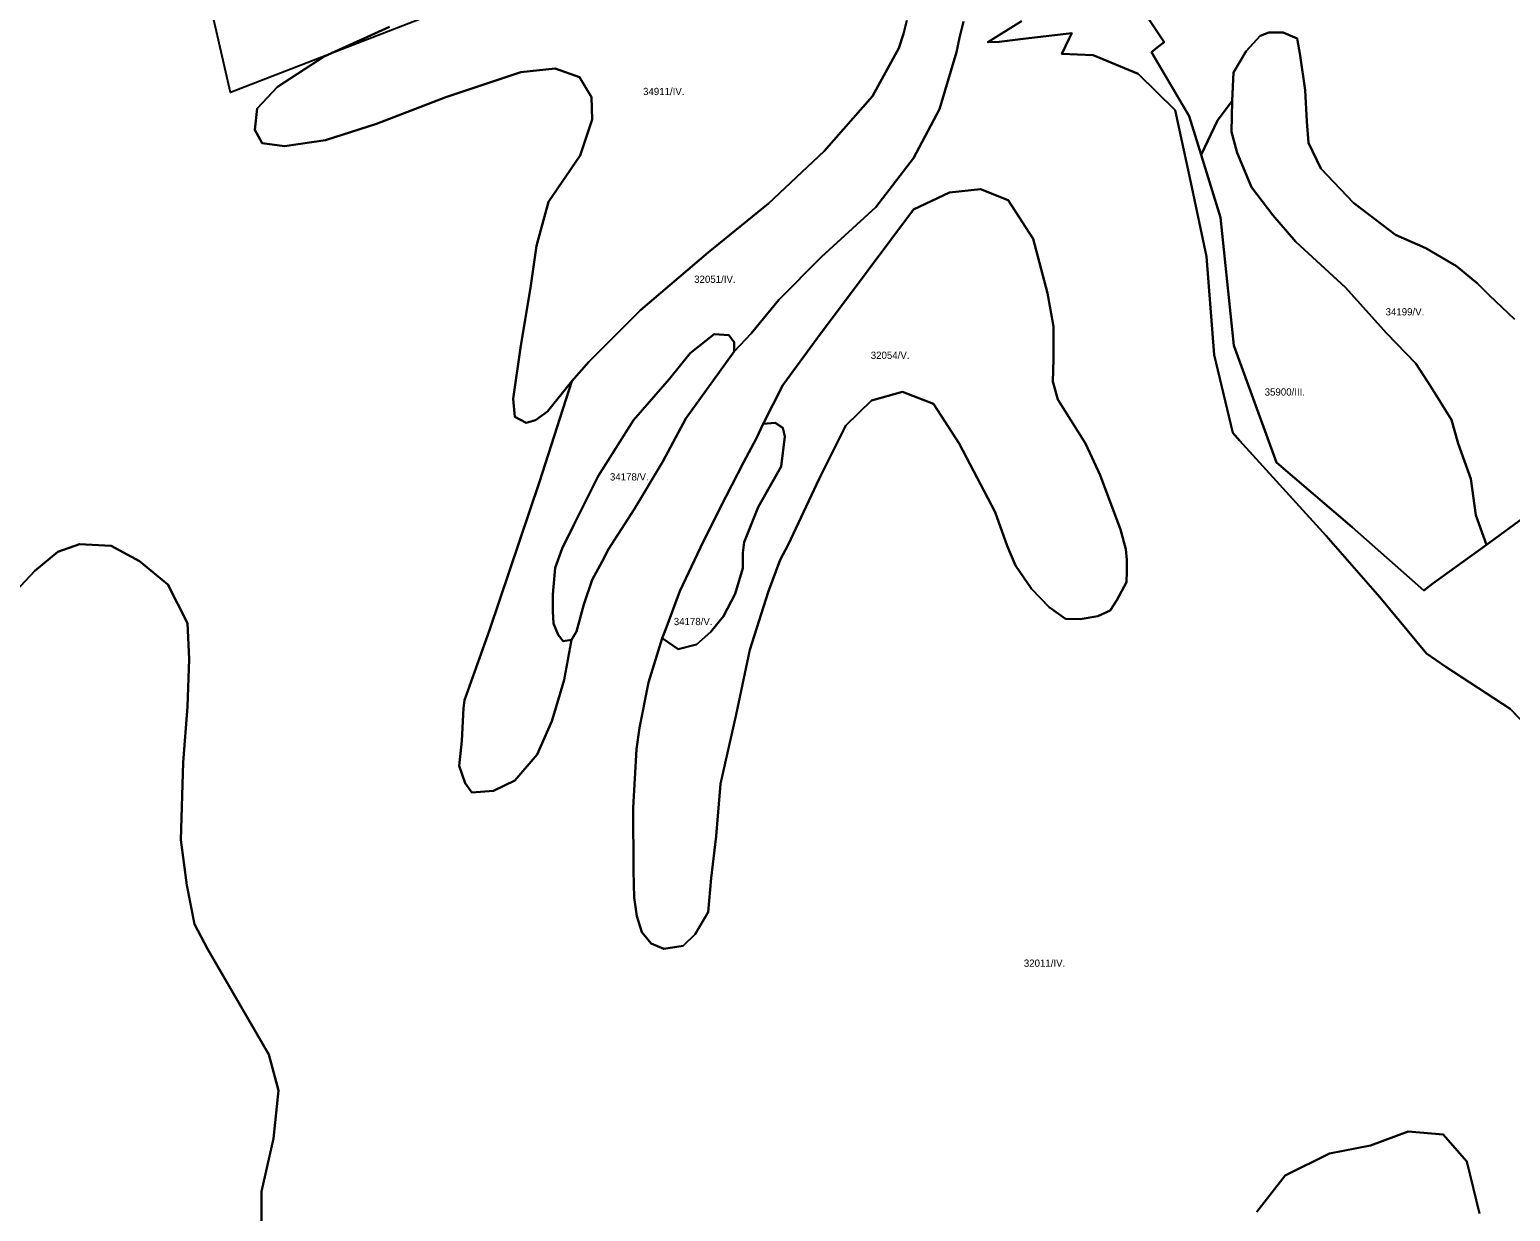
# Model space of a CAD drawing. Extents: x -521621 to -516761, y -1190184 to -1184927.
# Drawn here: x -520631 to -519813, y -1188092 to -1187439 of the extents above; entities that cross this region are included whole.
import ezdxf

# ---------------------------------------------------------------- set-up
doc = ezdxf.new("R2010")
doc.units = 0
doc.layers.add('BPEJ_s', color=7, linetype='Continuous')
doc.layers.add('odvodneni_s', color=7, linetype='Continuous')

msp = doc.modelspace()

# ---------------------------------------------------------------- linework, layer by layer
at = {"layer": 'BPEJ_s'}
for p, q in [((-520432.14, -1187437.52), (-520468.22, -1187453.88)), ((-520117.15, -1187443.67), (-520115.05, -1187434.6)), ((-520082.97, -1187434.36), (-520101.58, -1187446)), ((-520004.02, -1187445.95), (-520013.73, -1187431.67)), ((-520118.83, -1187451.64), (-520117.15, -1187443.67)), ((-520101.58, -1187446), (-520095.34, -1187445.82)), ((-520095.34, -1187445.82), (-520081.96, -1187444.27)), ((-520081.96, -1187444.27), (-520055.07, -1187440.98)), ((-520056.51, -1187444.08), (-520060.65, -1187452.57)), ((-520055.07, -1187440.98), (-520056.51, -1187444.08)), ((-520007.94, -1187449.05), (-520004.02, -1187445.95)), ((-519951.04, -1187442.61), (-519958.81, -1187450.94)), ((-519946.32, -1187440.67), (-519951.04, -1187442.61)), ((-519938.28, -1187440.67), (-519946.32, -1187440.67)), ((-519930.51, -1187444), (-519938.28, -1187440.67)), ((-519928.85, -1187453.44), (-519930.51, -1187444)), ((-520468.22, -1187453.88), (-520494.15, -1187470.8)), ((-520128.33, -1187482.99), (-520118.83, -1187451.64)), ((-520060.65, -1187452.57), (-520043.28, -1187453.19)), ((-520043.28, -1187453.19), (-520018.48, -1187463.53)), ((-520011.04, -1187451.53), (-520007.94, -1187449.05)), ((-519990.2, -1187487.01), (-520011.04, -1187451.53)), ((-519958.81, -1187450.94), (-519965.74, -1187462.87)), ((-519926.08, -1187472.59), (-519928.85, -1187453.44)), ((-520401.13, -1187476.44), (-520359.55, -1187462.56)), ((-520359.55, -1187462.56), (-520340.56, -1187460.66)), ((-520340.56, -1187460.66), (-520327.27, -1187465.42)), ((-520018.48, -1187463.53), (-519997.95, -1187483.56)), ((-519965.74, -1187462.87), (-519966.43, -1187478.47)), ((-520494.15, -1187470.8), (-520505.42, -1187482.65)), ((-520327.27, -1187465.42), (-520320.62, -1187476.34)), ((-520439.47, -1187491.11), (-520401.13, -1187476.44)), ((-520320.62, -1187476.34), (-520320.15, -1187488.69)), ((-519966.43, -1187478.47), (-519974.55, -1187489.31)), ((-519925.24, -1187489.8), (-519926.08, -1187472.59)), ((-520505.42, -1187482.65), (-520506.55, -1187494.49)), ((-520142.57, -1187510.07), (-520128.33, -1187482.99)), ((-519997.95, -1187483.56), (-519989.34, -1187523.63)), ((-519983.68, -1187508.23), (-519990.2, -1187487.01)), ((-520506.55, -1187494.49), (-520502.6, -1187501.82)), ((-520467.65, -1187500.13), (-520439.47, -1187491.11)), ((-520320.15, -1187488.69), (-520326.79, -1187508.65)), ((-519974.55, -1187489.31), (-519983.68, -1187508.23)), ((-519924.41, -1187501.73), (-519925.24, -1187489.8)), ((-520502.6, -1187501.82), (-520490.2, -1187503.52)), ((-520490.2, -1187503.52), (-520467.65, -1187500.13)), ((-519917.48, -1187515.89), (-519924.41, -1187501.73)), ((-520326.79, -1187508.65), (-520344.36, -1187534.3)), ((-520163.46, -1187537.15), (-520142.57, -1187510.07)), ((-519899.45, -1187534.76), (-519917.48, -1187515.89)), ((-520122.63, -1187529.08), (-520142.57, -1187538.58)), ((-520105.54, -1187527.18), (-520122.63, -1187529.08)), ((-520090.34, -1187533.35), (-520105.54, -1187527.18)), ((-519989.34, -1187523.63), (-519980.73, -1187564.56)), ((-520344.36, -1187534.3), (-520351.01, -1187558.53)), ((-520193.37, -1187564.71), (-520163.46, -1187537.15)), ((-520076.57, -1187554.73), (-520090.34, -1187533.35)), ((-519876.15, -1187552.52), (-519899.45, -1187534.76)), ((-520142.57, -1187538.58), (-520168.21, -1187572.79)), ((-519859.45, -1187559.82), (-519876.15, -1187552.52)), ((-520351.01, -1187558.53), (-520354.33, -1187581.81)), ((-520068.5, -1187584.66), (-520076.57, -1187554.73)), ((-519842.5, -1187569.89), (-519859.45, -1187559.82)), ((-520217.11, -1187588.46), (-520193.37, -1187564.71)), ((-519980.73, -1187564.56), (-519976.42, -1187618.85)), ((-519830.85, -1187579.42), (-519842.5, -1187569.89)), ((-520168.21, -1187572.79), (-520195.75, -1187609.37)), ((-520354.33, -1187581.81), (-520359.55, -1187613.64)), ((-520065.18, -1187603.19), (-520068.5, -1187584.66)), ((-519824.56, -1187585.83), (-519830.85, -1187579.42)), ((-519810.41, -1187599.15), (-519824.56, -1187585.83)), ((-520232.31, -1187606.99), (-520217.11, -1187588.46)), ((-520241.8, -1187616.97), (-520232.31, -1187606.99)), ((-520195.75, -1187609.37), (-520214.74, -1187635.5)), ((-520065.18, -1187621.25), (-520065.18, -1187603.19)), ((-520359.55, -1187613.64), (-520363.83, -1187643.1)), ((-520268.39, -1187654.03), (-520241.8, -1187616.97)), ((-519976.42, -1187618.85), (-519966.09, -1187661.93)), ((-520065.65, -1187633.6), (-520065.18, -1187621.25)), ((-520331.39, -1187633.36), (-520349.25, -1187689.02)), ((-520344.84, -1187650.23), (-520331.39, -1187633.36)), ((-520214.74, -1187635.5), (-520225.66, -1187656.88)), ((-520062.8, -1187643.57), (-520065.65, -1187633.6)), ((-520363.83, -1187643.1), (-520362.88, -1187653.08)), ((-520180.08, -1187657.83), (-520165.84, -1187644.05)), ((-520165.84, -1187644.05), (-520148.74, -1187639.3)), ((-520148.74, -1187639.3), (-520131.65, -1187645.95)), ((-520047.61, -1187667.8), (-520062.8, -1187643.57)), ((-520351.48, -1187654.98), (-520344.84, -1187650.23)), ((-520131.65, -1187645.95), (-520117.41, -1187667.8)), ((-520362.88, -1187653.08), (-520356.71, -1187656.4)), ((-520356.71, -1187656.4), (-520351.48, -1187654.98)), ((-520281.21, -1187677.78), (-520268.39, -1187654.03)), ((-520225.66, -1187656.88), (-520229.46, -1187664.95)), ((-520194.8, -1187687.28), (-520180.08, -1187657.83)), ((-520229.46, -1187664.95), (-520236.58, -1187678.26)), ((-520117.41, -1187667.8), (-520097.46, -1187705.81)), ((-520039.54, -1187685.38), (-520047.61, -1187667.8)), ((-519966.09, -1187661.93), (-519962.36, -1187666.24)), ((-519962.36, -1187666.24), (-519914.48, -1187718.92)), ((-520296.88, -1187703.91), (-520281.21, -1187677.78)), ((-520236.58, -1187678.26), (-520249.4, -1187703.44)), ((-520349.25, -1187689.02), (-520376.91, -1187770.9)), ((-520211.89, -1187723.86), (-520194.8, -1187687.28)), ((-520028.14, -1187715.31), (-520039.54, -1187685.38)), ((-520311.12, -1187726.24), (-520296.88, -1187703.91)), ((-520249.4, -1187703.44), (-520260.32, -1187725.29)), ((-520097.46, -1187705.81), (-520090.82, -1187724.34)), ((-520025.29, -1187726.24), (-520028.14, -1187715.31)), ((-520603.6, -1187723.39), (-520615.47, -1187727.67)), ((-520586.04, -1187724.34), (-520603.6, -1187723.39)), ((-520570.37, -1187732.89), (-520586.04, -1187724.34)), ((-520260.32, -1187725.29), (-520271.81, -1187749.37)), ((-520216.24, -1187732.15), (-520211.89, -1187723.86)), ((-520090.82, -1187724.34), (-520086.28, -1187735.18)), ((-519914.48, -1187718.92), (-519884.85, -1187752.71)), ((-520615.47, -1187727.67), (-520628.29, -1187738.12)), ((-520554.7, -1187745.72), (-520570.37, -1187732.89)), ((-520320.16, -1187743.09), (-520314.58, -1187733.08)), ((-520314.58, -1187733.08), (-520311.12, -1187726.24)), ((-520222.98, -1187750.07), (-520216.24, -1187732.15)), ((-520024.67, -1187732.15), (-520025.29, -1187726.24)), ((-520024.67, -1187738.44), (-520024.67, -1187732.15)), ((-520628.29, -1187738.12), (-520644.18, -1187755.37)), ((-520086.28, -1187735.18), (-520077.45, -1187748.21)), ((-520024.9, -1187744.48), (-520024.67, -1187738.44)), ((-520543.78, -1187767.1), (-520554.7, -1187745.72)), ((-520324.81, -1187756.81), (-520320.16, -1187743.09)), ((-520271.81, -1187749.37), (-520279.71, -1187770.77)), ((-520232.98, -1187781.94), (-520222.98, -1187750.07)), ((-520077.45, -1187748.21), (-520067.68, -1187758.21)), ((-520030.25, -1187754.49), (-520024.9, -1187744.48)), ((-520328.77, -1187771.7), (-520324.81, -1187756.81)), ((-520067.68, -1187758.21), (-520058.61, -1187764.72)), ((-520033.97, -1187760.07), (-520030.25, -1187754.49)), ((-519884.85, -1187752.71), (-519859.15, -1187783.88)), ((-520058.61, -1187764.72), (-520050.48, -1187764.96)), ((-520050.48, -1187764.96), (-520040.71, -1187763.33)), ((-520040.71, -1187763.33), (-520033.97, -1187760.07)), ((-520542.83, -1187787.05), (-520543.78, -1187767.1)), ((-520376.91, -1187770.9), (-520390.76, -1187809.62)), ((-520331.56, -1187776.35), (-520328.77, -1187771.7)), ((-520279.71, -1187770.77), (-520281.57, -1187775.42)), ((-520335.74, -1187798.45), (-520331.56, -1187776.35)), ((-520281.57, -1187775.42), (-520289.01, -1187799.85)), ((-520240.65, -1187817.53), (-520232.98, -1187781.94)), ((-520543.78, -1187813.18), (-520542.83, -1187787.05)), ((-519859.15, -1187783.88), (-519848.45, -1187791.27)), ((-519848.45, -1187791.27), (-519812.86, -1187814.51)), ((-520339, -1187809.62), (-520335.74, -1187798.45)), ((-520289.01, -1187799.85), (-520294.12, -1187824.97)), ((-520546.15, -1187844.06), (-520543.78, -1187813.18)), ((-520391.36, -1187814.13), (-520392.31, -1187832.18)), ((-520390.76, -1187809.62), (-520391.36, -1187814.13)), ((-520342.46, -1187821.26), (-520339, -1187809.62)), ((-519812.86, -1187814.51), (-519793.87, -1187834.17)), ((-520350.53, -1187839.79), (-520342.46, -1187821.26)), ((-520249.26, -1187855.91), (-520240.65, -1187817.53)), ((-520392.31, -1187832.18), (-520393.74, -1187845.96)), ((-520294.12, -1187824.97), (-520295.75, -1187836.84)), ((-520362.88, -1187854.04), (-520350.53, -1187839.79)), ((-520295.75, -1187836.84), (-520297.61, -1187869.17)), ((-520547.58, -1187886.82), (-520546.15, -1187844.06)), ((-520393.74, -1187845.96), (-520390.42, -1187855.46)), ((-520390.42, -1187855.46), (-520386.62, -1187860.69)), ((-520374.75, -1187859.74), (-520362.88, -1187854.04)), ((-520251.58, -1187884.76), (-520249.26, -1187855.91)), ((-520386.62, -1187860.69), (-520374.75, -1187859.74)), ((-520297.61, -1187869.17), (-520297.38, -1187904.07)), ((-520544.25, -1187912), (-520547.58, -1187886.82)), ((-520254.37, -1187908.02), (-520251.58, -1187884.76)), ((-520297.38, -1187904.07), (-520296.92, -1187918.72)), ((-520539.98, -1187933.38), (-520544.25, -1187912)), ((-520256, -1187926.86), (-520254.37, -1187908.02)), ((-520296.92, -1187918.72), (-520295.52, -1187928.96)), ((-520295.52, -1187928.96), (-520292.73, -1187937.8)), ((-520263.2, -1187938.96), (-520256, -1187926.86)), ((-520532.75, -1187947.05), (-520539.98, -1187933.38)), ((-520292.73, -1187937.8), (-520287.62, -1187944.08)), ((-520287.62, -1187944.08), (-520280.64, -1187947.1)), ((-520280.64, -1187947.1), (-520269.95, -1187945.48)), ((-520269.95, -1187945.48), (-520263.2, -1187938.96)), ((-520510.2, -1187986.21), (-520532.75, -1187947.05)), ((-520498.93, -1188005.46), (-520510.2, -1187986.21)), ((-520493.62, -1188025.37), (-520498.93, -1188005.46)), ((-520496.27, -1188051.92), (-520493.62, -1188025.37)), ((-520502.91, -1188081.12), (-520496.27, -1188051.92)), ((-519869.15, -1188047.97), (-519890.09, -1188055.83)), ((-519849.96, -1188049.72), (-519869.15, -1188047.97)), ((-519836.87, -1188064.56), (-519849.96, -1188049.72)), ((-519912.78, -1188060.2), (-519937.21, -1188072.42)), ((-519890.09, -1188055.83), (-519912.78, -1188060.2)), ((-519829.89, -1188093.37), (-519836.87, -1188064.56)), ((-519937.21, -1188072.42), (-519952.92, -1188092.5)), ((-520502.91, -1188129.57), (-520502.91, -1188081.12))]:
    msp.add_line(p, q, dxfattribs=at)
for points in [[(-520146.23, -1187433.97), (-520148.13, -1187441.35), (-520150.64, -1187449.26), (-520165.36, -1187475.87), (-520191.95, -1187506.27), (-520222.81, -1187535.25), (-520256.05, -1187562.33), (-520293.56, -1187594.17), (-520322.05, -1187622.67), (-520331.39, -1187633.36), (-520344.84, -1187650.23), (-520351.48, -1187654.98), (-520356.71, -1187656.4), (-520362.88, -1187653.08), (-520363.83, -1187643.1), (-520359.55, -1187613.64), (-520354.33, -1187581.81), (-520351.01, -1187558.53), (-520344.36, -1187534.3), (-520326.79, -1187508.65), (-520320.15, -1187488.69), (-520320.62, -1187476.34), (-520327.27, -1187465.42), (-520340.56, -1187460.66), (-520359.55, -1187462.56), (-520401.13, -1187476.44), (-520439.47, -1187491.11), (-520467.65, -1187500.13), (-520490.2, -1187503.52), (-520502.6, -1187501.82), (-520506.55, -1187494.49), (-520505.42, -1187482.65), (-520494.15, -1187470.8), (-520468.22, -1187453.88), (-520432.14, -1187437.52)], [(-520115.05, -1187434.6), (-520117.15, -1187443.67), (-520118.83, -1187451.64), (-520128.33, -1187482.99), (-520142.57, -1187510.07), (-520163.46, -1187537.15), (-520193.37, -1187564.71), (-520217.11, -1187588.46), (-520232.31, -1187606.99), (-520241.8, -1187616.97), (-520241.8, -1187611.74), (-520244.65, -1187607.94), (-520252.72, -1187607.47), (-520266.02, -1187617.92), (-520277.41, -1187632.17), (-520297.36, -1187654.98), (-520316.82, -1187685.86), (-520330.12, -1187712.46), (-520336.76, -1187725.77), (-520340.62, -1187736.57), (-520342.02, -1187751.23), (-520342.02, -1187760.53), (-520341.55, -1187767.28), (-520339, -1187773.56), (-520336.21, -1187777.05), (-520331.56, -1187776.35), (-520335.74, -1187798.45), (-520339, -1187809.62), (-520342.46, -1187821.26), (-520350.53, -1187839.79), (-520362.88, -1187854.04), (-520374.75, -1187859.74), (-520386.62, -1187860.69), (-520390.42, -1187855.46), (-520393.74, -1187845.96), (-520392.31, -1187832.18), (-520391.36, -1187814.13), (-520390.76, -1187809.62), (-520376.91, -1187770.9), (-520349.25, -1187689.02), (-520331.39, -1187633.36), (-520322.05, -1187622.67), (-520293.56, -1187594.17), (-520256.05, -1187562.33), (-520222.81, -1187535.25), (-520191.95, -1187506.27), (-520165.36, -1187475.87), (-520150.64, -1187449.26), (-520148.13, -1187441.35), (-520146.23, -1187433.97)], [(-519793.87, -1187834.17), (-519812.86, -1187814.51), (-519848.45, -1187791.27), (-519859.15, -1187783.88), (-519884.85, -1187752.71), (-519914.48, -1187718.92), (-519962.36, -1187666.24), (-519966.09, -1187661.93), (-519976.42, -1187618.85), (-519980.73, -1187564.56), (-519989.34, -1187523.63), (-519997.95, -1187483.56), (-520018.48, -1187463.53), (-520043.28, -1187453.19), (-520060.65, -1187452.57), (-520056.51, -1187444.08), (-520055.07, -1187440.98), (-520081.96, -1187444.27), (-520095.34, -1187445.82), (-520101.58, -1187446), (-520082.97, -1187434.36)], [(-520013.73, -1187431.67), (-520004.02, -1187445.95), (-520007.94, -1187449.05), (-520011.04, -1187451.53), (-519990.2, -1187487.01), (-519983.68, -1187508.23), (-519972.98, -1187543.02), (-519965.66, -1187613.68), (-519941.97, -1187678.27), (-519900.23, -1187714.04), (-519860.56, -1187749.15), (-519855.59, -1187745.21), (-519826, -1187723.77), (-519803.25, -1187707.28)], [(-519803.25, -1187707.28), (-519826, -1187723.77), (-519831.85, -1187707.43), (-519834.59, -1187687.4), (-519841.54, -1187667.79), (-519845.36, -1187654.66), (-519856.46, -1187636.62), (-519865.05, -1187623.57), (-519881.14, -1187606.92), (-519903.89, -1187581.66), (-519931.35, -1187556.41), (-519944.11, -1187541.7), (-519955.76, -1187526.16), (-519963.8, -1187507.28), (-519966.85, -1187495.62), (-519966.43, -1187478.47), (-519965.74, -1187462.87), (-519958.81, -1187450.94), (-519951.04, -1187442.61), (-519946.32, -1187440.67), (-519938.28, -1187440.67), (-519930.51, -1187444), (-519928.85, -1187453.44), (-519926.08, -1187472.59), (-519925.24, -1187489.8), (-519924.41, -1187501.73), (-519917.48, -1187515.89), (-519899.45, -1187534.76), (-519876.15, -1187552.52), (-519859.45, -1187559.82), (-519842.5, -1187569.89), (-519830.85, -1187579.42), (-519824.56, -1187585.83), (-519810.41, -1187599.15)], [(-520644.18, -1187755.37), (-520628.29, -1187738.12), (-520615.47, -1187727.67), (-520603.6, -1187723.39), (-520586.04, -1187724.34), (-520570.37, -1187732.89), (-520554.7, -1187745.72), (-520543.78, -1187767.1), (-520542.83, -1187787.05), (-520543.78, -1187813.18), (-520546.15, -1187844.06), (-520547.58, -1187886.82), (-520544.25, -1187912), (-520539.98, -1187933.38), (-520532.75, -1187947.05), (-520510.2, -1187986.21), (-520498.93, -1188005.46), (-520493.62, -1188025.37), (-520496.27, -1188051.92), (-520502.91, -1188081.12), (-520502.91, -1188105.01)], [(-519952.92, -1188092.5), (-519937.21, -1188072.42), (-519912.78, -1188060.2), (-519890.09, -1188055.83), (-519869.15, -1188047.97), (-519849.96, -1188049.72), (-519836.87, -1188064.56), (-519829.89, -1188093.37)]]:
    msp.add_lwpolyline(points, dxfattribs=at)
for points in [[(-519983.68, -1187508.23), (-519974.55, -1187489.31), (-519966.43, -1187478.47), (-519966.85, -1187495.62), (-519963.8, -1187507.28), (-519955.76, -1187526.16), (-519944.11, -1187541.7), (-519931.35, -1187556.41), (-519903.89, -1187581.66), (-519881.14, -1187606.92), (-519865.05, -1187623.57), (-519856.46, -1187636.62), (-519845.36, -1187654.66), (-519841.54, -1187667.79), (-519834.59, -1187687.4), (-519831.85, -1187707.43), (-519826, -1187723.77), (-519855.59, -1187745.21), (-519860.56, -1187749.15), (-519900.23, -1187714.04), (-519941.97, -1187678.27), (-519965.66, -1187613.68), (-519972.98, -1187543.02)], [(-520281.57, -1187775.42), (-520272.74, -1187781.47), (-520262.51, -1187778.91), (-520254.6, -1187771.93), (-520247.63, -1187763.33), (-520241.12, -1187751), (-520236.93, -1187736.81), (-520236.93, -1187728.2), (-520236.11, -1187722.44), (-520228.51, -1187702.96), (-520215.69, -1187680.63), (-520213.79, -1187664), (-520214.74, -1187659.25), (-520219.01, -1187656.4), (-520225.66, -1187656.88), (-520214.74, -1187635.5), (-520195.75, -1187609.37), (-520168.21, -1187572.79), (-520142.57, -1187538.58), (-520122.63, -1187529.08), (-520105.54, -1187527.18), (-520090.34, -1187533.35), (-520076.57, -1187554.73), (-520068.5, -1187584.66), (-520065.18, -1187603.19), (-520065.18, -1187621.25), (-520065.65, -1187633.6), (-520062.8, -1187643.57), (-520047.61, -1187667.8), (-520039.54, -1187685.38), (-520028.14, -1187715.31), (-520025.29, -1187726.24), (-520024.67, -1187732.15), (-520024.67, -1187738.44), (-520024.9, -1187744.48), (-520030.25, -1187754.49), (-520033.97, -1187760.07), (-520040.71, -1187763.33), (-520050.48, -1187764.96), (-520058.61, -1187764.72), (-520067.68, -1187758.21), (-520077.45, -1187748.21), (-520086.28, -1187735.18), (-520090.82, -1187724.34), (-520097.46, -1187705.81), (-520117.41, -1187667.8), (-520131.65, -1187645.95), (-520148.74, -1187639.3), (-520165.84, -1187644.05), (-520180.08, -1187657.83), (-520194.8, -1187687.28), (-520211.89, -1187723.86), (-520216.24, -1187732.15), (-520222.98, -1187750.07), (-520232.98, -1187781.94), (-520240.65, -1187817.53), (-520249.26, -1187855.91), (-520251.58, -1187884.76), (-520254.37, -1187908.02), (-520256, -1187926.86), (-520263.2, -1187938.96), (-520269.95, -1187945.48), (-520280.64, -1187947.1), (-520287.62, -1187944.08), (-520292.73, -1187937.8), (-520295.52, -1187928.96), (-520296.92, -1187918.72), (-520297.38, -1187904.07), (-520297.61, -1187869.17), (-520295.75, -1187836.84), (-520294.12, -1187824.97), (-520289.01, -1187799.85)], [(-520331.56, -1187776.35), (-520336.21, -1187777.05), (-520339, -1187773.56), (-520341.55, -1187767.28), (-520342.02, -1187760.53), (-520342.02, -1187751.23), (-520340.62, -1187736.57), (-520336.76, -1187725.77), (-520330.12, -1187712.46), (-520316.82, -1187685.86), (-520297.36, -1187654.98), (-520277.41, -1187632.17), (-520266.02, -1187617.92), (-520252.72, -1187607.47), (-520244.65, -1187607.94), (-520241.8, -1187611.74), (-520241.8, -1187616.97), (-520268.39, -1187654.03), (-520281.21, -1187677.78), (-520296.88, -1187703.91), (-520311.12, -1187726.24), (-520314.58, -1187733.08), (-520320.16, -1187743.09), (-520324.81, -1187756.81), (-520328.77, -1187771.7)], [(-520281.57, -1187775.42), (-520279.71, -1187770.77), (-520271.81, -1187749.37), (-520260.32, -1187725.29), (-520249.4, -1187703.44), (-520236.58, -1187678.26), (-520229.46, -1187664.95), (-520225.66, -1187656.88), (-520219.01, -1187656.4), (-520214.74, -1187659.25), (-520213.79, -1187664), (-520215.69, -1187680.63), (-520228.51, -1187702.96), (-520236.11, -1187722.44), (-520236.93, -1187728.2), (-520236.93, -1187736.81), (-520241.12, -1187751), (-520247.63, -1187763.33), (-520254.6, -1187771.93), (-520262.51, -1187778.91), (-520272.74, -1187781.47)]]:
    msp.add_lwpolyline(points, close=True, dxfattribs=at)
at = {"layer": 'odvodneni_s'}
msp.add_lwpolyline([(-520593.76, -1187152.58), (-520541.54, -1187164.45), (-520515.42, -1187165.48), (-520393.78, -1187200.38), (-520326.56, -1187211.63), (-520292.57, -1187219), (-520207.51, -1187243.56), (-520108.49, -1187272.64), (-520108.69, -1187281.29), (-520123.82, -1187309.68), (-520145.11, -1187328.82), (-520175.98, -1187347.03), (-520205.14, -1187354.13), (-520224.13, -1187362.31), (-520261.94, -1187373.88), (-520520.06, -1187473.85)], close=True, dxfattribs=at)

# ---------------------------------------------------------------- texts
at = {"layer": 'BPEJ_s'}
for s, p in [('34911/IV.', (-520292.07, -1187475.28)), ('32051/IV.', (-520263.83, -1187579.04)), ('34199/V.', (-519881.73, -1187597.05)), ('32054/V.', (-520166.24, -1187621.08)), ('35900/III.', (-519948.54, -1187641.35)), ('34178/V.', (-520310.37, -1187688.26)), ('34178/V.', (-520275.09, -1187768.21)), ('32011/IV.', (-520081.64, -1187957.01))]:
    msp.add_text(s, height=4, dxfattribs=at).set_placement(p)

doc.saveas('drawing.dxf')
